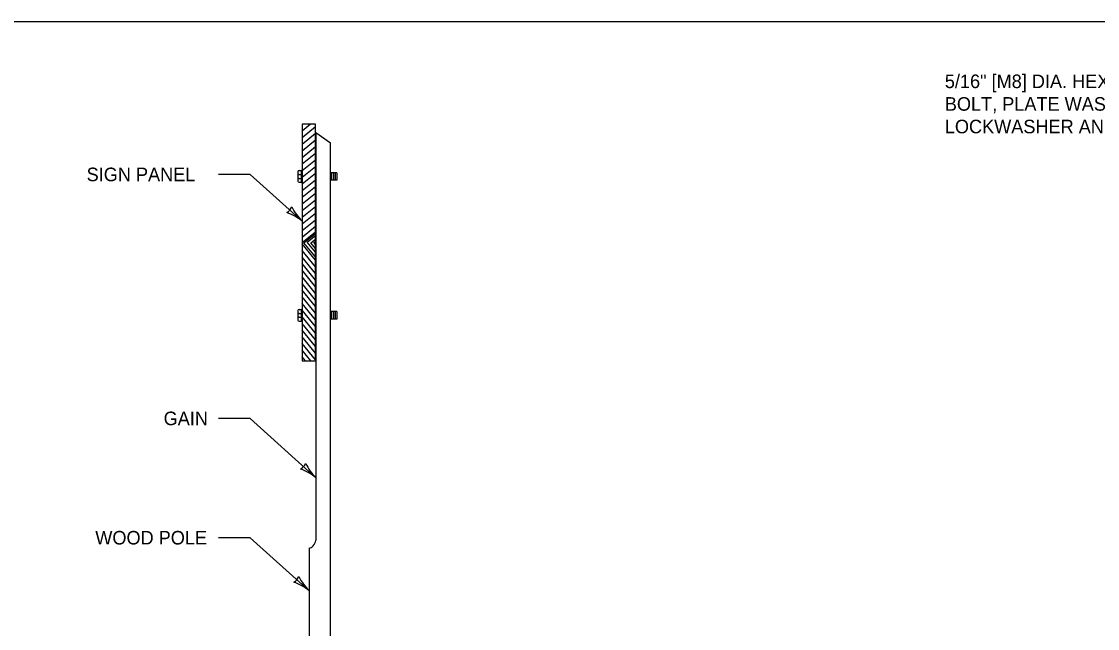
# Model space of a CAD drawing. Extents: x 49991.4 to 50021, y 49987.6 to 50011.4.
# Drawn here: x 50004.078 to 50008.843, y 49996.314 to 49998.999 of the extents above; entities that cross this region are included whole.
import ezdxf

# ---------------------------------------------------------------- set-up
doc = ezdxf.new("R2010")
doc.units = 0
for name, color, linetype in [('Level 1', 7, 'Continuous'), ('Level 2', 7, 'Continuous'), ('Level 3', 7, 'Continuous')]:
    doc.layers.add(name, color=color, linetype=linetype)

msp = doc.modelspace()

# ---------------------------------------------------------------- linework, layer by layer
at = {"layer": 'Level 1'}
for p, q in [((50005.3203, 49998.516), (50005.3566, 49998.5454)), ((50005.3203, 49998.4866), (50005.3791, 49998.5342)), ((50005.3203, 49998.4572), (50005.3791, 49998.5048)), ((50005.3818, 49998.5087), (50005.4465, 49998.4619)), ((50005.3818, 49998.5087), (50005.3818, 49996.703)), ((50005.3203, 49998.4278), (50005.3791, 49998.4754)), ((50005.3203, 49998.3984), (50005.3791, 49998.446)), ((50005.4465, 49995.4192), (50005.4465, 49998.4619)), ((50005.3203, 49998.369), (50005.3791, 49998.4166)), ((50005.3203, 49998.3396), (50005.3791, 49998.3872)), ((50005.3021, 49998.3347), (50005.3021, 49998.2927)), ((50005.3069, 49998.3395), (50005.3184, 49998.3395)), ((50005.3184, 49998.2858), (50005.3184, 49998.3414)), ((50005.3184, 49998.3414), (50005.3198, 49998.3414)), ((50005.3184, 49998.3395), (50005.3184, 49998.2879)), ((50005.3198, 49998.2858), (50005.3198, 49998.3414)), ((50005.3203, 49998.3102), (50005.3791, 49998.3578)), ((50005.3021, 49998.3222), (50005.3184, 49998.3222)), ((50005.3021, 49998.3051), (50005.3184, 49998.3051)), ((50005.3069, 49998.2879), (50005.3184, 49998.2879)), ((50005.3203, 49998.2808), (50005.3791, 49998.3284)), ((50005.3203, 49998.2514), (50005.3791, 49998.299)), ((50005.4742, 49998.3298), (50005.4465, 49998.3298)), ((50005.4742, 49998.2967), (50005.4465, 49998.2967)), ((50005.4499, 49998.3298), (50005.4499, 49998.2967)), ((50005.4592, 49998.3298), (50005.4592, 49998.2967)), ((50005.4661, 49998.3298), (50005.4661, 49998.2967)), ((50005.4742, 49998.3298), (50005.4742, 49998.2967)), ((50005.3198, 49998.2858), (50005.3184, 49998.2858)), ((50005.3203, 49998.222), (50005.3791, 49998.2696)), ((50005.3203, 49998.1926), (50005.3791, 49998.2402)), ((50005.3203, 49998.1632), (50005.3791, 49998.2108)), ((50005.3203, 49998.1338), (50005.3791, 49998.1814)), ((50005.3203, 49998.1044), (50005.3791, 49998.152)), ((50005.3203, 49998.075), (50005.3791, 49998.1226)), ((50005.3203, 49998.0456), (50005.3791, 49998.0932)), ((50005.3203, 49998.0215), (50005.3791, 49998.0691)), ((50005.3287, 49998.0202), (50005.3791, 49998.0609)), ((50005.3435, 49998.0233), (50005.3791, 49998.052)), ((50005.3791, 49997.9436), (50005.3203, 49998.0162)), ((50005.3791, 49997.9579), (50005.3287, 49998.0202)), ((50005.3791, 49997.9794), (50005.3435, 49998.0233)), ((50005.3587, 49998.0201), (50005.3791, 49998.0366)), ((50005.3791, 49997.9948), (50005.3587, 49998.0201)), ((50005.3723, 49998.0209), (50005.3791, 49998.0264)), ((50005.3791, 49998.0125), (50005.3723, 49998.0209)), ((50005.3791, 49997.9142), (50005.3203, 49997.9868)), ((50005.3791, 49997.8848), (50005.3203, 49997.9574)), ((50005.3791, 49997.8554), (50005.3203, 49997.928)), ((50005.3791, 49997.826), (50005.3203, 49997.8986)), ((50005.3791, 49997.7966), (50005.3203, 49997.8692)), ((50005.3791, 49997.7672), (50005.3203, 49997.8398)), ((50005.3791, 49997.7378), (50005.3203, 49997.8104)), ((50005.3791, 49997.7084), (50005.3203, 49997.781)), ((50005.3021, 49997.7206), (50005.3021, 49997.6786)), ((50005.3069, 49997.7254), (50005.3184, 49997.7254)), ((50005.3184, 49997.6717), (50005.3184, 49997.7273)), ((50005.3184, 49997.7273), (50005.3198, 49997.7273)), ((50005.3184, 49997.7254), (50005.3184, 49997.6738)), ((50005.3198, 49997.6717), (50005.3198, 49997.7273)), ((50005.3791, 49997.679), (50005.3203, 49997.7516)), ((50005.3791, 49997.6496), (50005.3203, 49997.7222)), ((50005.4742, 49997.7157), (50005.4465, 49997.7157)), ((50005.4499, 49997.7157), (50005.4499, 49997.6826)), ((50005.4592, 49997.7157), (50005.4592, 49997.6826)), ((50005.4661, 49997.7157), (50005.4661, 49997.6826)), ((50005.4742, 49997.7157), (50005.4742, 49997.6826)), ((50005.3021, 49997.7081), (50005.3184, 49997.7081)), ((50005.3021, 49997.691), (50005.3184, 49997.691)), ((50005.3069, 49997.6738), (50005.3182, 49997.6738)), ((50005.3198, 49997.6717), (50005.3184, 49997.6717)), ((50005.3791, 49997.6202), (50005.3203, 49997.6928)), ((50005.4742, 49997.6826), (50005.4465, 49997.6826)), ((50005.3791, 49997.5908), (50005.3203, 49997.6634)), ((50005.3791, 49997.5614), (50005.3203, 49997.634)), ((50005.3791, 49997.532), (50005.3203, 49997.6046)), ((50005.3791, 49997.5026), (50005.3203, 49997.5752)), ((50005.3594, 49997.4975), (50005.3203, 49997.5458)), ((50005.3357, 49997.4975), (50005.3203, 49997.5164)), ((50005.3513, 49996.6693), (50005.3513, 49995.5658))]:
    msp.add_line(p, q, dxfattribs=at)
for points in [[(49999.3835, 49998.9992), (50016.7501, 49998.9992), (50016.7501, 49987.7988), (49999.3835, 49987.7988)], [(50005.3203, 49998.5454), (50005.3203, 49997.4975), (50005.3791, 49997.4975), (50005.3791, 49998.5454)]]:
    msp.add_lwpolyline(points, close=True, dxfattribs=at)
for centre, radius, start, end in [((50005.3069, 49998.3347), 0.00484, 89.981, 179.981), ((50005.307, 49998.3271), 0.00486, 179.9258, 269.9258), ((50005.3069, 49998.3174), 0.0048, 89.3154, 179.3154), ((50005.3069, 49998.3099), 0.00479, 180.1198, 270.1198), ((50005.3069, 49998.3003), 0.00482, 90.0061, 180.0061), ((50005.3069, 49998.2927), 0.0048, 180, 270), ((50005.3069, 49997.7206), 0.00482, 90.2522, 180.2522), ((50005.307, 49997.713), 0.00489, 179.78, 269.78), ((50005.3069, 49997.7033), 0.00481, 89.2382, 179.2382), ((50005.3069, 49997.6958), 0.00482, 179.9913, 269.9913), ((50005.3069, 49997.6862), 0.00482, 90.0312, 180.0312), ((50005.3069, 49997.6786), 0.0048, 180, 270)]:
    msp.add_arc(centre, radius, start, end, dxfattribs=at)
msp.add_ellipse((50005.3604, 49996.6976), major_axis=(-0.016, -0.0268), ratio=0.577668, start_param=0.381328, end_param=2.097284, dxfattribs=at)
at = {"layer": 'Level 3'}
for p, q in [((50005.0904, 49998.3228), (50004.9502, 49998.3228)), ((50005.0904, 49998.3228), (50005.3203, 49998.1157)), ((50005.0904, 49997.2433), (50004.9502, 49997.2433)), ((50005.0904, 49997.2433), (50005.3818, 49996.9808)), ((50005.0904, 49996.7155), (50004.9502, 49996.7155)), ((50005.0904, 49996.7155), (50005.3513, 49996.4805))]:
    msp.add_line(p, q, dxfattribs=at)
for centre, radius, start, end in [((50005.225, 49998.2015), 0.0548, 300.1255, 335.8478), ((50005.1784, 49997.9445), 0.2223, 50.3471, 70.5306), ((50005.4846, 49998.2809), 0.233, 205.9095, 225.1593), ((50005.2865, 49997.0666), 0.0548, 300.1255, 335.8479), ((50005.2346, 49996.8002), 0.233, 50.814, 70.0639), ((50005.5373, 49997.1397), 0.2223, 205.4427, 225.6262), ((50005.256, 49996.5663), 0.0548, 300.1286, 335.8509), ((50005.5068, 49996.6394), 0.2223, 205.4458, 225.6293), ((50005.2041, 49996.2999), 0.233, 50.8171, 70.0669)]:
    msp.add_arc(centre, radius, start, end, dxfattribs=at)

# ---------------------------------------------------------------- texts
at = {"layer": 'Level 2'}
for s, p in [('5/16" [M8] DIA. HEX HEAD', (50008.1667, 49998.7047)), ('BOLT, PLATE WASHER,', (50008.1667, 49998.6047)), ('LOCKWASHER AND NUT', (50008.1667, 49998.5047)), ('SIGN PANEL', (50004.3662, 49998.2928)), ('GAIN', (50004.7072, 49997.2133)), ('WOOD POLE', (50004.4045, 49996.6855))]:
    msp.add_text(s, height=0.06, dxfattribs=at).set_placement(p)

doc.saveas('drawing.dxf')
